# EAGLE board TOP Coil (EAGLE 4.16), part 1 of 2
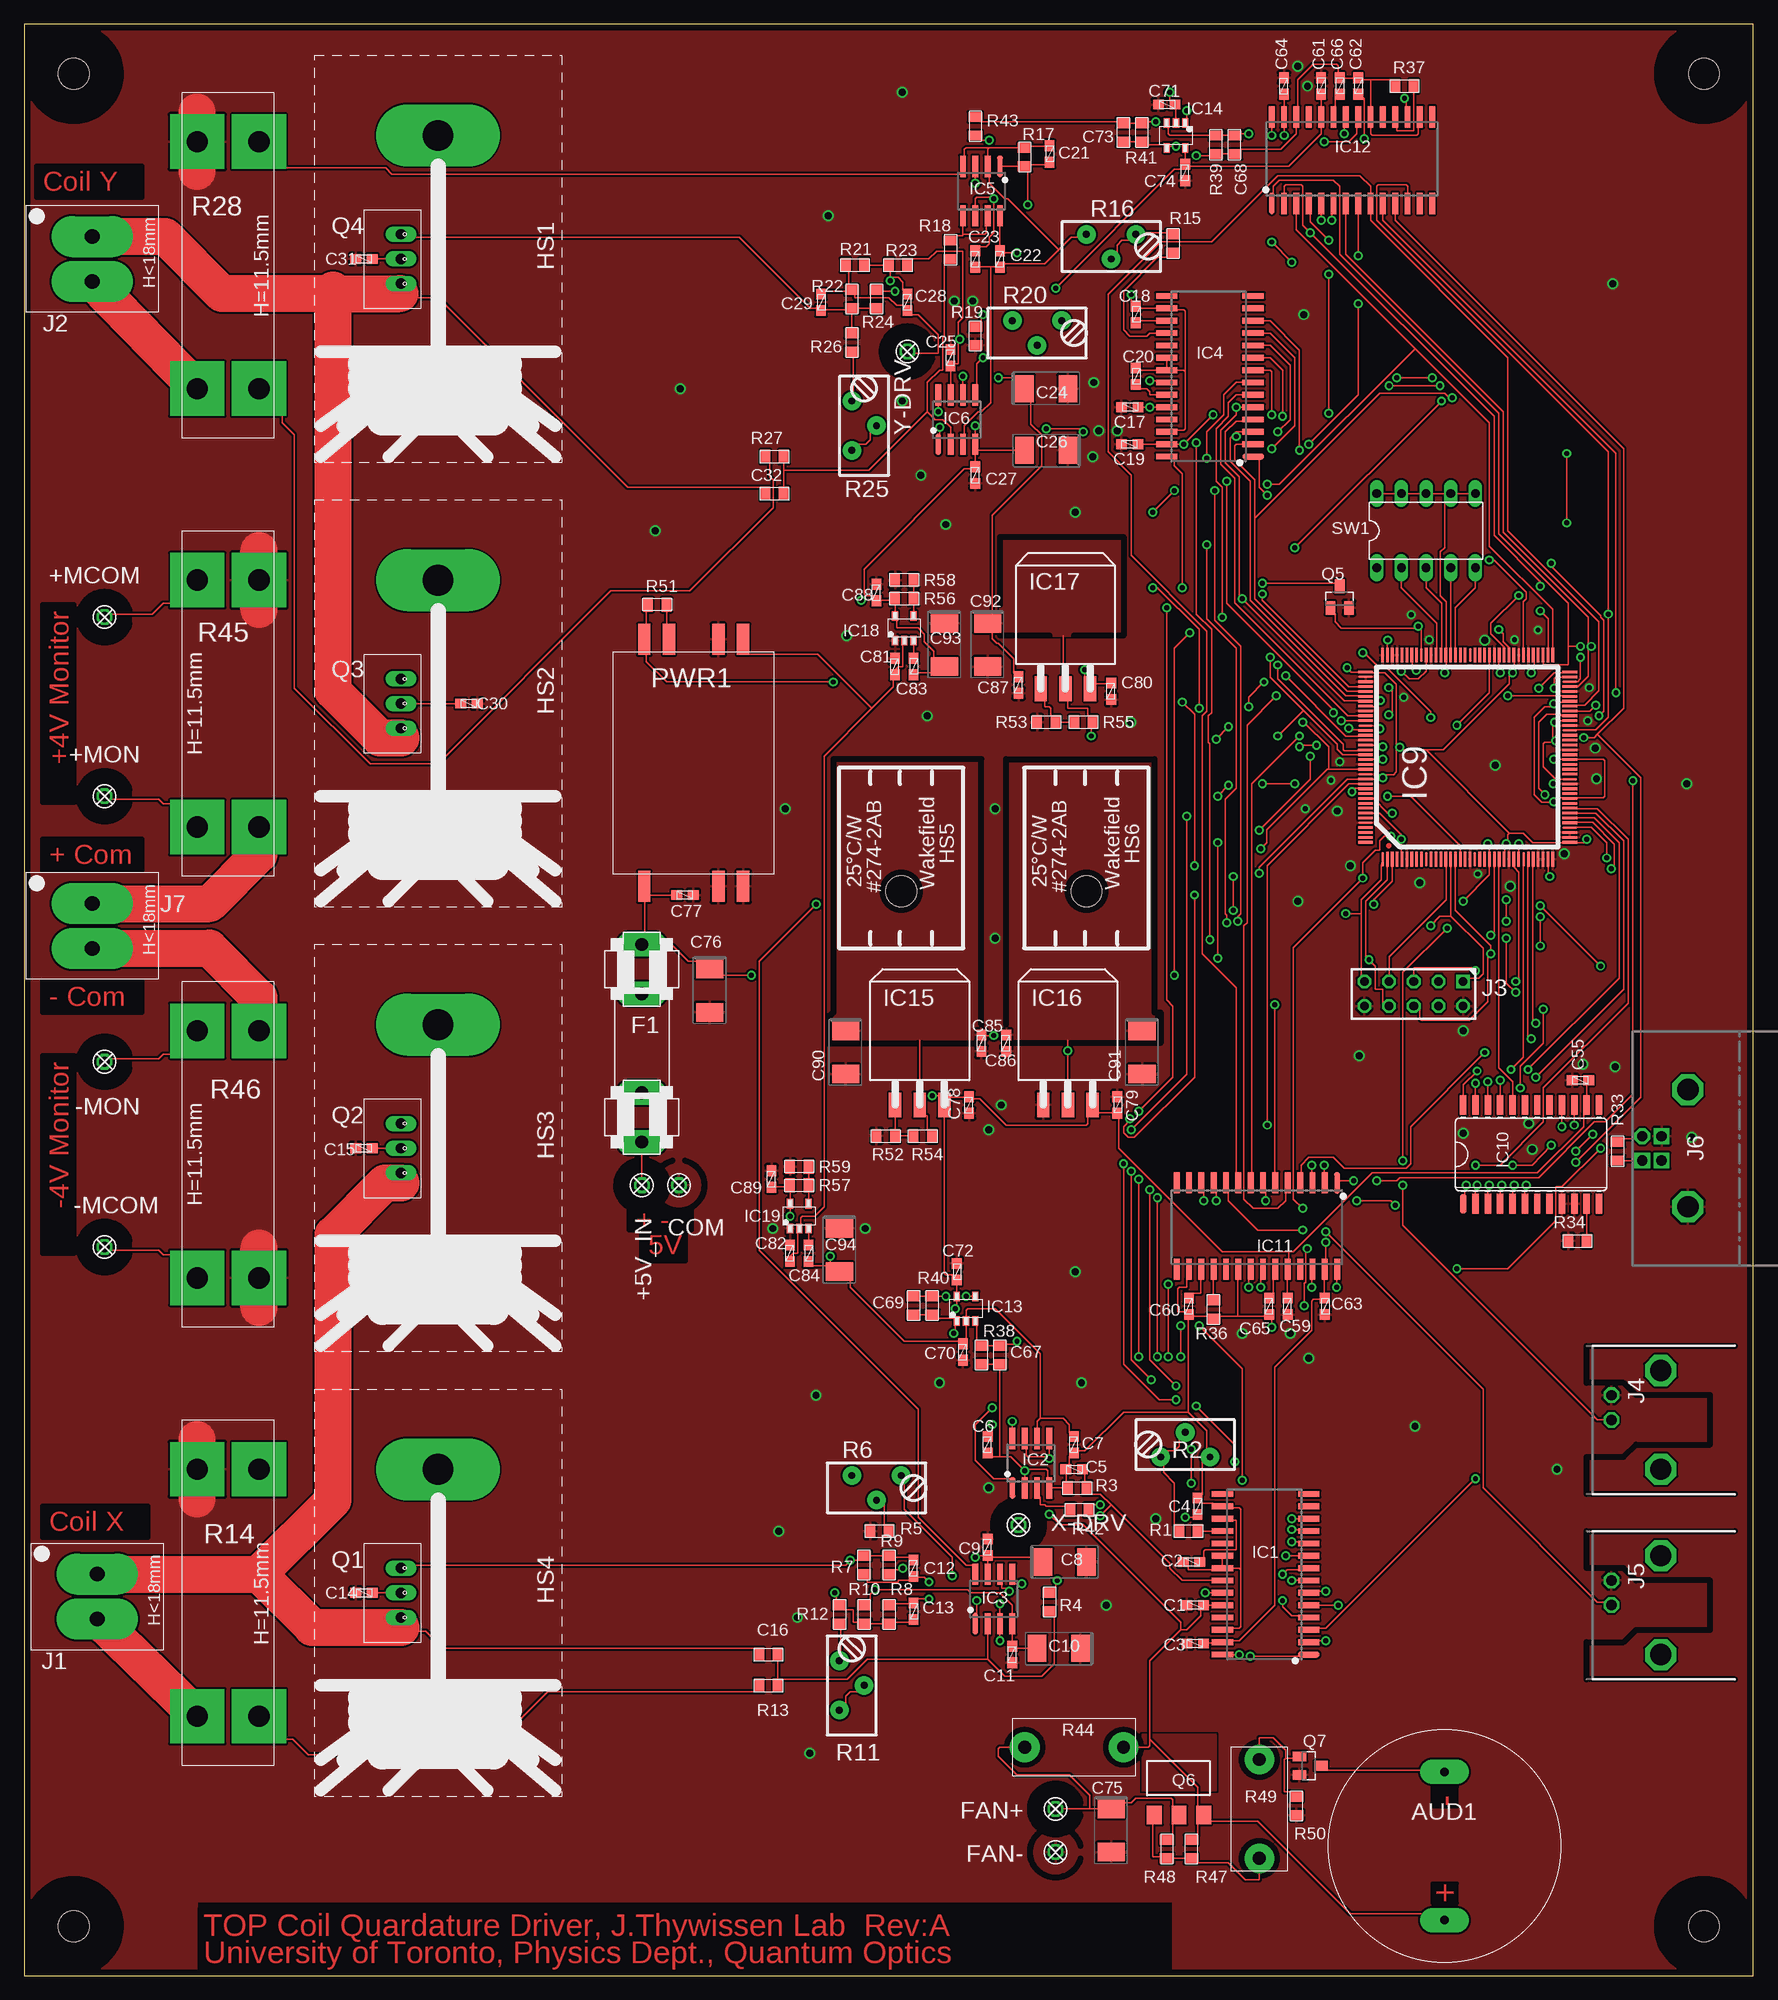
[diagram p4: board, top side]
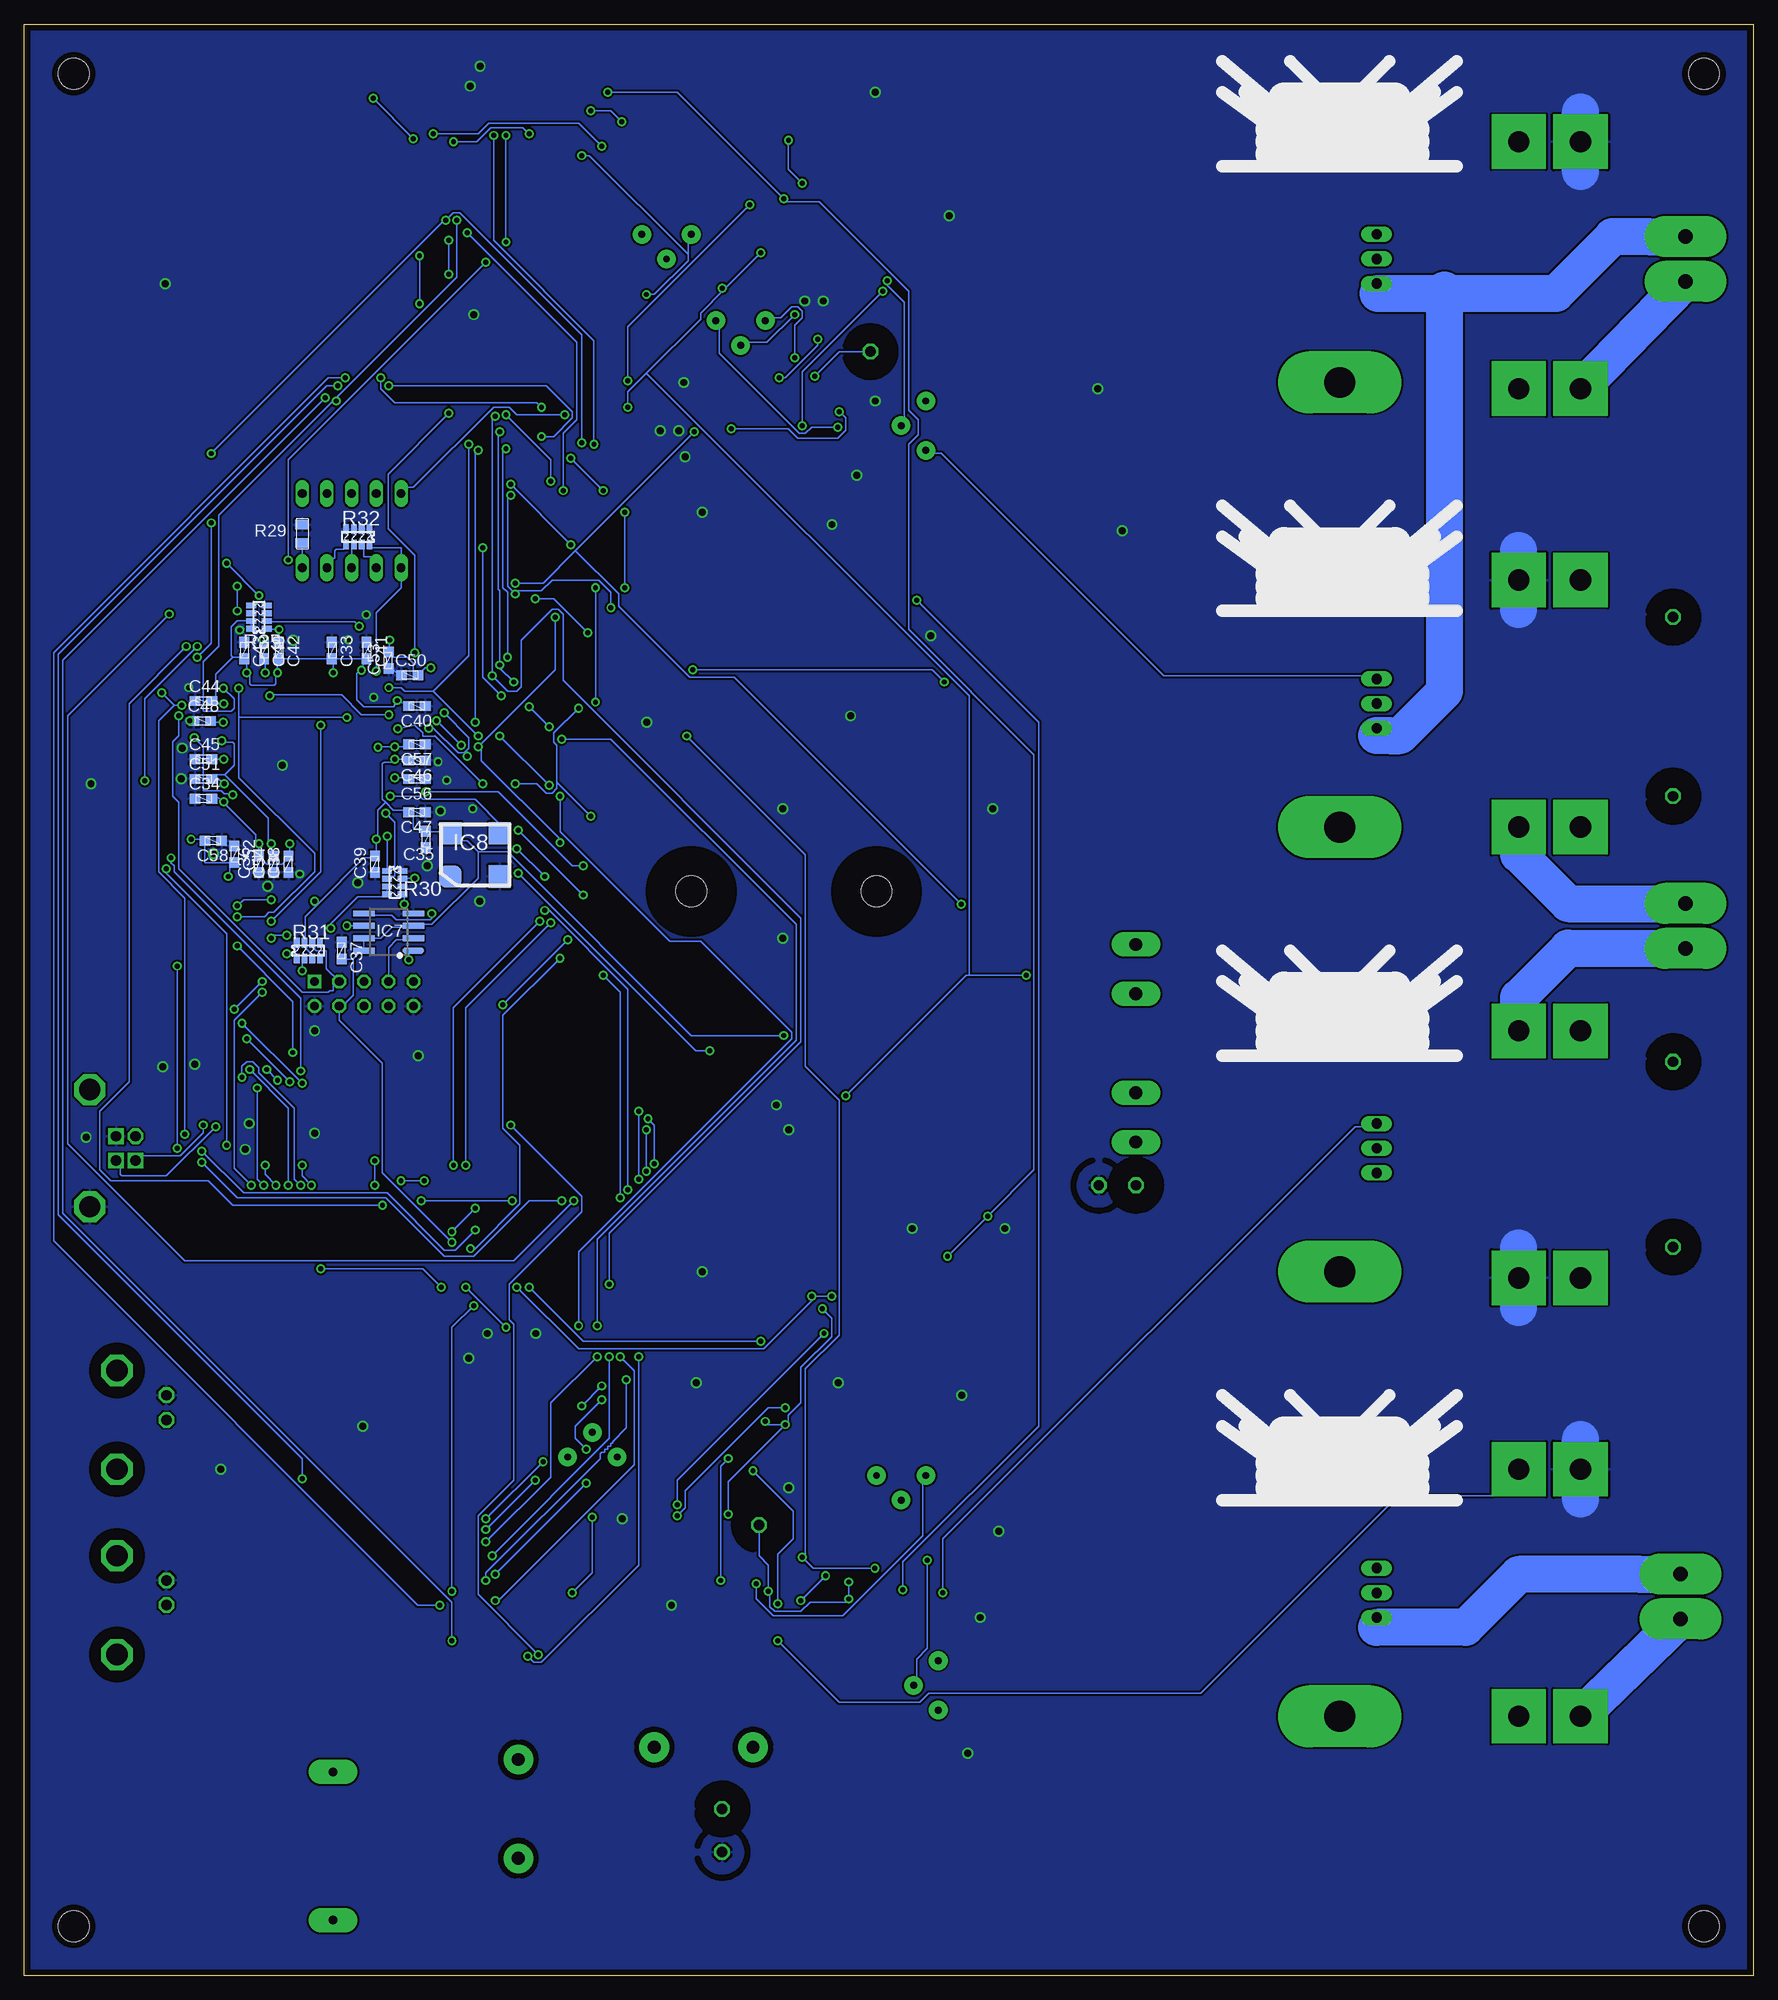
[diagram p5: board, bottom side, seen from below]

Size 177.8 x 200.66 mm. Coordinates in mm from the lower left corner, seen from the top.
Outline: 0,0 177.8,0 177.8,200.66 0,200.66 0,0
Copper layers (1*16): Top 0.035mm / dielectric 1.5mm / Bottom 0.035mm
Design rules "DRC standard check (7mil trace and gap, 20mil drill, etc)": minimum track width 7mil, minimum drill 20mil, track to track 7mil, track to pad 7mil, pad to pad 7mil, via to via 7mil, smd to smd 7mil, copper to edge 25mil, drill to drill 8mil, minimum pad ring 10mil, minimum via ring 8mil, stop-mask expansion 4mil, vias tented up to drill 0mil, thermal gap 10mil
Holes 3.17 mm at 5.08,5.08 172.72,5.08 5.08,195.58 172.72,195.58
tKeepout: area -0.2,-0.2 to 10.3,10.3; area 167.5,-0.2 to 178,10.3; area -0.2,190.3 to 10.3,200.8; area 167.5,190.3 to 178,200.8
bKeepout: area -0.2,-0.2 to 10.3,10.3; area 167.5,-0.2 to 178,10.3; area -0.2,190.3 to 10.3,200.8; area 167.5,190.3 to 178,200.8
tRestrict: 58 lines
bRestrict: 6 lines
vRestrict: area 83.2,95.9 to 98.4,125.1; area 101,95.9 to 116.2,125.1; area 100.3,137.8 to 113,148

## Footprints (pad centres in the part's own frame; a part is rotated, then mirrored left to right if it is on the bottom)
TP-0.042 = drill 1.067 octagon: TP 0,0
AUDIO_DEVICE1 = drill 0.889 pad 2.54 long: + -7.62,0; - 7.62,0
1608(0603) = smd 1.1 x 1: 1 -0.85,0; 2 0.85,0
EIA-6032 = smd 1.905 x 2.794: + 2.54,0; - -1.905,0
2012(0805) = smd 1.016 x 1.397: 1 -1.27,0; 2 0.635,0
FUSE = drill 1.321 pad 2.54 long: 1A -10.16,0; 1B -5.08,0; 2A 10.16,0; 2B 5.08,0
HEATSINK_529802B02(AAVID) = drill 3.175 pad 6.35 long: 1 -12.7,0; 2 12.7,0
HEATSINK-3 = hole 3.175: 3.429,0
SOIC28 = smd 0.6 x 2.2: 1 -7.62,-3.81; 2 -6.35,-3.81; 3 -5.08,-3.81; 4 -3.81,-3.81; 5 -2.54,-3.81; 6 -1.27,-3.81; 7 0,-3.81; 8 1.27,-3.81; 9 2.54,-3.81; 10 3.81,-3.81; 11 5.08,-3.81; 12 6.35,-3.81; 13 7.62,-3.81; 14 8.89,-3.81; 15 8.89,5.08; 16 7.62,5.08; 17 6.35,5.08; 18 5.08,5.08; 19 3.81,5.08; 20 2.54,5.08; 21 1.27,5.08; 22 0,5.08; 23 -1.27,5.08; 24 -2.54,5.08; 25 -3.81,5.08; 26 -5.08,5.08; 27 -6.35,5.08; 28 -7.62,5.08
SOIC-8 = smd 0.6 x 2.2: 1 -1.27,-2.54; 2 0,-2.54; 3 1.27,-2.54; 4 2.54,-2.54; 5 2.54,2.54; 6 1.27,2.54; 7 0,2.54; 8 -1.27,2.54
CSX750(CITIZEN_OSC) = smd 2.286 x 2.286: 1 -2.54,-1.27; 2 2.54,-1.27; 3 2.54,3.175; 4 -2.54,3.175
TQFP-144 = smd 1.5 x 0.27: 1 -10.29,8.29; 2 -10.29,7.79; 3 -10.29,7.29; 4 -10.29,6.79; 5 -10.29,6.29; 6 -10.29,5.79; 7 -10.29,5.29; 8 -10.29,4.79; 9 -10.29,4.29; 10 -10.29,3.79; 11 -10.29,3.29; 12 -10.29,2.79; 13 -10.29,2.29; 14 -10.29,1.79; 15 -10.29,1.29; 16 -10.29,0.79; 17 -10.29,0.29; 18 -10.29,-0.21; 19 -10.29,-0.71; 20 -10.29,-1.21; 21 -10.29,-1.71; 22 -10.29,-2.21; 23 -10.29,-2.71; 24 -10.29,-3.21; 25 -10.29,-3.71; 26 -10.29,-4.21; 27 -10.29,-4.71; 28 -10.29,-5.21; 29 -10.29,-5.71; 30 -10.29,-6.21; 31 -10.29,-6.71; 32 -10.29,-7.21; 33 -10.29,-7.71; 34 -10.29,-8.21; 35 -10.29,-8.71; 36 -10.29,-9.21; 73 10.71,-9.21; 74 10.71,-8.71; 75 10.71,-8.21; 76 10.71,-7.71; 77 10.71,-7.21; 78 10.71,-6.71; 79 10.71,-6.21; 80 10.71,-5.71; 81 10.71,-5.21; 82 10.71,-4.71; 83 10.71,-4.21; 84 10.71,-3.71; 85 10.71,-3.21; 86 10.71,-2.71; 87 10.71,-2.21; 88 10.71,-1.71; 89 10.71,-1.21; 90 10.71,-0.71; 91 10.71,-0.21; 92 10.71,0.29; 93 10.71,0.79; 94 10.71,1.29; 95 10.71,1.79; 96 10.71,2.29; 97 10.71,2.79; 98 10.71,3.29; 99 10.71,3.79; 100 10.71,4.29; 101 10.71,4.79; 102 10.71,5.29; 103 10.71,5.79; 104 10.71,6.29; 105 10.71,6.79; 106 10.71,7.29; 107 10.71,7.79; 108 10.71,8.29 | smd 0.27 x 1.5: 37 -8.54,-10.96; 38 -8.04,-10.96; 39 -7.54,-10.96; 40 -7.04,-10.96; 41 -6.54,-10.96; 42 -6.04,-10.96; 43 -5.54,-10.96; 44 -5.04,-10.96; 45 -4.54,-10.96; 46 -4.04,-10.96; 47 -3.54,-10.96; 48 -3.04,-10.96; 49 -2.54,-10.96; 50 -2.04,-10.96; 51 -1.54,-10.96; 52 -1.04,-10.96; 53 -0.54,-10.96; 54 -0.04,-10.96; 55 0.46,-10.96; 56 0.96,-10.96; 57 1.46,-10.96; 58 1.96,-10.96; 59 2.46,-10.96; 60 2.96,-10.96; 61 3.46,-10.96; 62 3.96,-10.96; 63 4.46,-10.96; 64 4.96,-10.96; 65 5.46,-10.96; 66 5.96,-10.96; 67 6.46,-10.96; 68 6.96,-10.96; 69 7.46,-10.96; 70 7.96,-10.96; 71 8.46,-10.96; 72 8.96,-10.96; 109 8.96,10.04; 110 8.46,10.04; 111 7.96,10.04; 112 7.46,10.04; 113 6.96,10.04; 114 6.46,10.04; 115 5.96,10.04; 116 5.46,10.04; 117 4.96,10.04; 118 4.46,10.04; 119 3.96,10.04; 120 3.46,10.04; 121 2.96,10.04; 122 2.46,10.04; 123 1.96,10.04; 124 1.46,10.04; 125 0.96,10.04; 126 0.46,10.04; 127 -0.04,10.04; 128 -0.54,10.04; 129 -1.04,10.04; 130 -1.54,10.04; 131 -2.04,10.04; 132 -2.54,10.04; 133 -3.04,10.04; 134 -3.54,10.04; 135 -4.04,10.04; 136 -4.54,10.04; 137 -5.04,10.04; 138 -5.54,10.04; 139 -6.04,10.04; 140 -6.54,10.04; 141 -7.04,10.04; 142 -7.54,10.04; 143 -8.04,10.04; 144 -8.54,10.04
SOIC-24-0.3 = smd 0.66 x 2.032: 1 -6.35,-5.08; 2 -5.08,-5.08; 3 -3.81,-5.08; 4 -2.54,-5.08; 5 -1.27,-5.08; 6 0,-5.08; 7 1.27,-5.08; 8 2.54,-5.08; 9 3.81,-5.08; 10 5.08,-5.08; 11 6.35,-5.08; 12 7.62,-5.08; 13 7.62,5.08; 14 6.35,5.08; 15 5.08,5.08; 16 3.81,5.08; 17 2.54,5.08; 18 1.27,5.08; 19 0,5.08; 20 -1.27,5.08; 21 -2.54,5.08; 22 -3.81,5.08; 23 -5.08,5.08; 24 -6.35,5.08
SOT23-5 = smd 0.635 x 0.991: 1 -0.635,-1.27; 2 0.318,-1.27; 3 1.27,-1.27; 4 1.27,1.27; 5 -0.635,1.27
TO263 = smd 1.27 x 2.54: 1 -2.54,0; 2 0,0; 3 2.54,0
CONN-2TERM = drill 1.511 pad 4.2 long: 1 0,2.31; 2 0,-2.31
CONN-2X5-BLASTER = drill 0.889 square: 1 0,5.08 | drill 0.889 octagon: 2 2.54,5.08; 3 0,2.54; 4 2.54,2.54; 5 0,0; 6 2.54,0; 7 0,-2.54; 8 2.54,-2.54; 9 0,-5.08; 10 2.54,-5.08
CONN-BNC-AMP-TYPE3HORIZ = drill 1.067 octagon: CONDUCTOR 0,-12.7; SHIELD -2.54,-12.7 | drill 2.184 octagon: P$1 -5.08,-7.62; P$2 5.08,-7.62
CONN-USB_AU-Y1007 = drill 1.067 octagon: 1 2.5,0 | drill 1.067 square: 2 0,0; 3 0,-2; 4 2.5,-2 | drill 2.184 octagon: S1 -4.75,-4.7; S2 7.3,-4.7
CC3-XXXXX-E(TDK_DC-DC) = smd 3.175 x 1.27: +VIN -12.7,5.08; +VOUT 12.7,5.08; -VIN -12.7,-5.08; -VOUT 12.7,-5.08; COM 12.7,-2.54; RC -12.7,-2.54; TRM 12.7,2.54
TO220-VERTICAL = drill 1.067 long: 1 -2.54,0; 2 0,0; 3 2.54,0
SOT23 = smd 1 x 1.4: 1 -0.953,-0.953; 2 0.953,-0.953; 3 0,1.27
SOT223 = smd 1.524 x 1.905: 1 -2.54,-2.54; 2 0,-2.54; 3 2.54,-2.54
BOURNS-3296Y = drill 0.711 pad 1.905 round: CCW 2.54,1.27; CW -2.54,1.27; W 0,-1.27
OHMITE_650 = drill 2.184 pad 5.588 square: 1A -12.7,2.54; 1B -12.7,-3.81; 2A 12.7,2.54; 2B 12.7,-3.81
PANASONIC_EXB-V8V(QUAD-R-PACK) = smd 1 x 0.59: 1A -0.8,1.2; 1B 0.8,1.2; 2A -0.8,0.4; 2B 0.8,0.4; 3A -0.8,-0.4; 3B 0.8,-0.4; 4A -0.8,-1.2; 4B 0.8,-1.2
PASSIVE_0.4" = drill 1.321 pad 3.048 round: 1 -5.08,0; 2 5.08,0
DIL10 = drill 0.889 long: 1 -6.35,-3.81; 2 -3.81,-3.81; 3 -1.27,-3.81; 4 1.27,-3.81; 5 3.81,-3.81; 6 3.81,3.81; 7 1.27,3.81; 8 -1.27,3.81; 9 -3.81,3.81; 10 -6.35,3.81

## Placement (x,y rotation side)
+5V_IN  [TP-0.042]  63.5,81.28 270 top
+MCOM  [TP-0.042]  8.26,139.7 180 top
+MON  [TP-0.042]  8.26,121.28 180 top
-MCOM  [TP-0.042]  8.26,74.93 180 top
-MON  [TP-0.042]  8.26,93.98 180 top
AUD1  MSR516W*  [AUDIO_DEVICE1]  146.05,13.34 90 top
C1  0.1uF  [1608(0603)]  120.4,38.1 0 top
C2  0.1uF  [1608(0603)]  120.02,42.55 0 top
C3  0.1uF  [1608(0603)]  120.4,34.16 180 top
C4  0.1uF  [1608(0603)]  120.65,48.26 270 top
C5  0.1uF  [1608(0603)]  107.95,52.07 0 top
C6  0.1uF  [1608(0603)]  99.06,54.61 90 top
C7  0.1uF  [1608(0603)]  107.95,54.61 90 top
C8  33uF*  [EIA-6032]  107.31,42.55 180 top
C9  0.1uF  [1608(0603)]  99.06,44.07 90 top
C10  33uF*  [EIA-6032]  106.05,33.66 0 top
C11  0.1uF  [1608(0603)]  101.6,33.02 90 top
C12  1uF  [1608(0603)]  91.44,41.91 90 top
C13  1uF  [1608(0603)]  91.44,37.47 270 top
C14  0.1uF  [1608(0603)]  34.92,39.37 0 top
C15  0.1uF  [1608(0603)]  34.92,85.09 180 top
C16  22pF  [2012(0805)]  76.83,33.02 0 top
C17  0.1uF  [1608(0603)]  113.67,161.29 0 top
C18  0.1uF  [1608(0603)]  114.3,170.81 270 top
C19  0.1uF  [1608(0603)]  113.67,157.48 180 top
C20  0.1uF  [1608(0603)]  114.3,164.47 270 top
C21  0.1uF  [1608(0603)]  105.41,187.32 270 top
C22  0.1uF  [1608(0603)]  100.33,176.53 90 top
C23  0.1uF  [1608(0603)]  97.79,176.53 90 top
C24  33uF*  [EIA-6032]  105.41,163.19 180 top
C25  0.1uF  [1608(0603)]  95.25,166.37 90 top
C26  33uF*  [EIA-6032]  104.78,156.84 0 top
C27  0.1uF  [1608(0603)]  97.79,154.31 90 top
C28  1uF  [1608(0603)]  90.81,172.09 90 top
C29  1uF  [1608(0603)]  81.92,172.09 270 top
C30  0.1uF  [1608(0603)]  45.72,130.81 180 top
C31  0.1uF  [1608(0603)]  34.92,176.53 180 top
C32  22pF  [2012(0805)]  77.47,152.4 0 top
C33  0.1uF  [1608(0603)]  146.18,136.27 270 bottom
C34  0.1uF  [1608(0603)]  159.38,121.03 0 bottom
C35  0.1uF  [1608(0603)]  136.53,116.84 270 bottom
C36  0.1uF  [1608(0603)]  153.67,114.3 90 bottom
C37  0.1uF  [1608(0603)]  145.16,105.41 90 bottom
C38  0.1uF  [1608(0603)]  150.62,114.3 90 bottom
C39  0.1uF  [1608(0603)]  141.73,114.3 90 bottom
C40  0.1uF  [1608(0603)]  137.41,130.56 180 bottom
C41  0.1uF  [1608(0603)]  142.62,136.27 270 bottom
C42  0.1uF  [1608(0603)]  151.64,136.27 270 bottom
C43  0.1uF  [1608(0603)]  155.19,136.27 270 bottom
C44  0.1uF  [1608(0603)]  159.38,131.06 0 bottom
C45  0.1uF  [1608(0603)]  159.38,125.09 0 bottom
C46  0.1uF  [1608(0603)]  137.41,124.97 180 bottom
C47  0.1uF  [1608(0603)]  137.41,119.63 180 bottom
C48  0.1uF  [1608(0603)]  159.51,129.03 0 bottom
C49  0.1uF  [1608(0603)]  153.16,136.27 270 bottom
C50  0.1uF  [1608(0603)]  138.18,133.73 0 bottom
C51  0.1uF  [1608(0603)]  159.38,123.06 0 bottom
C52  0.1uF  [1608(0603)]  156.21,115.32 270 bottom
C53  0.1uF  [1608(0603)]  140.34,135.25 90 bottom
C54  0.1uF  [1608(0603)]  152.15,114.3 90 bottom
C55  0.1uF  [1608(0603)]  160.02,92.08 180 top
C56  0.1uF  [1608(0603)]  137.41,123.06 180 bottom
C57  0.1uF  [1608(0603)]  137.41,126.62 180 bottom
C58  0.1uF  [1608(0603)]  158.37,116.71 180 bottom
C59  0.1uF  [1608(0603)]  129.92,68.83 90 top
C60  0.1uF  [1608(0603)]  119.76,68.83 90 top
C61  0.1uF  [1608(0603)]  133.35,194.31 270 top
C62  0.1uF  [1608(0603)]  137.16,194.31 270 top
C63  0.1uF  [1608(0603)]  133.73,68.83 270 top
C64  0.1uF  [1608(0603)]  129.54,194.31 90 top
C65  0.1uF  [1608(0603)]  128.02,68.83 90 top
C66  0.1uF  [1608(0603)]  135.25,194.31 270 top
C67  27nF  [2012(0805)]  100.33,64.14 90 top
C68  27nF  [2012(0805)]  124.46,188.59 90 top
C69  27nF  [2012(0805)]  91.44,68.58 270 top
C70  0.1uF  [1608(0603)]  96.52,64.14 90 top
C71  0.1uF  [1608(0603)]  117.47,192.41 0 top
C72  0.1uF  [1608(0603)]  95.89,72.39 270 top
C73  27nF  [2012(0805)]  113.03,189.87 90 top
C74  0.1uF  [1608(0603)]  119.38,185.42 90 top
C75  33uF*  [EIA-6032]  111.76,14.61 90 top
C76  33uF*  [EIA-6032]  70.48,100.97 90 top
C77  0.1uF  [1608(0603)]  67.94,111.12 180 top
C78  0.1uF  [1608(0603)]  97.16,89.53 90 top
C79  0.1uF  [1608(0603)]  112.39,89.53 270 top
C80  0.1uF  [1608(0603)]  111.76,132.08 90 top
C81  0.1uF  [1608(0603)]  89.53,134.62 90 top
C82  0.1uF  [1608(0603)]  78.74,74.3 90 top
C83  0.1uF  [1608(0603)]  91.44,134.62 270 top
C84  0.1uF  [1608(0603)]  80.64,74.3 270 top
C85  0.1uF  [1608(0603)]  98.42,95.89 90 top
C86  0.1uF  [1608(0603)]  100.97,95.89 90 top
C87  0.1uF  [1608(0603)]  102.23,132.72 90 top
C88  0.1uF  [1608(0603)]  87.63,142.24 90 top
C89  0.1uF  [1608(0603)]  76.83,81.92 90 top
C90  33uF*  [EIA-6032]  84.45,94.61 90 top
C91  33uF*  [EIA-6032]  114.94,94.61 90 top
C92  33uF*  [EIA-6032]  99.06,136.53 90 top
C93  33uF*  [EIA-6032]  94.61,136.53 90 top
C94  33uF*  [EIA-6032]  83.82,74.3 90 top
COM  [TP-0.042]  67.31,81.28 270 top
F1  1A  [FUSE]  63.5,95.89 90 top
FAN+  [TP-0.042]  106.05,17.14 180 top
FAN-  [TP-0.042]  106.05,12.7 180 top
HS1  529802B02500G  [HEATSINK_529802B02(AAVID)]  42.55,176.53 270 top
HS2  529802B02500G  [HEATSINK_529802B02(AAVID)]  42.55,130.81 270 top
HS3  529802B02500G  [HEATSINK_529802B02(AAVID)]  42.55,85.09 270 top
HS4  529802B02500G  [HEATSINK_529802B02(AAVID)]  42.55,39.37 270 top
HS5  274-2AB  [HEATSINK-3]  90.17,114.94 270 top
HS6  274-2AB  [HEATSINK-3]  109.22,114.94 270 top
IC1  AD9752ARZ  [SOIC28]  128.27,40.64 90 top
IC2  AD603AR  [SOIC-8]  102.87,52.7 0 top
IC3  AD810AR  [SOIC-8]  99.06,38.73 0 top
IC4  AD9752ARZ  [SOIC28]  122.56,163.83 90 top
IC5  AD603AR  [SOIC-8]  99.06,183.51 180 top
IC6  AD810AR  [SOIC-8]  95.25,160.02 0 top
IC7  EPCS4  [SOIC-8]  140.34,106.68 90 bottom
IC8  80MHz*  [CSX750(CITIZEN_OSC)]  131.44,114.3 0 bottom
IC9  EP2C8T144C6  [TQFP-144]  147.96,125.09 90 top
IC10  802600*  [SOIC-24-0.3]  154.31,84.45 0 top
IC11  AD9752ARZ  [SOIC28]  127.38,77.72 180 top
IC12  AD9752ARZ  [SOIC28]  135.89,186.06 0 top
IC13  AD8614ART  [SOT23-5]  96.52,68.58 0 top
IC14  AD8614ART  [SOT23-5]  118.75,189.23 180 top
IC15  LM1086-ADJ  [TO263]  92.08,89.53 0 top
IC16  LM1086-ADJ  [TO263]  107.31,89.53 0 top
IC17  LM1086-ADJ  [TO263]  107.06,132.33 0 top
IC18  LT1964ES5-BYP  [SOT23-5]  90.17,138.56 0 top
IC19  LT1964ES5-BYP  [SOT23-5]  79.38,78.11 0 top
J1  LPP-5.00/90*  [CONN-2TERM]  7.49,38.99 0 top
J2  LPP-5.00/90*  [CONN-2TERM]  6.99,176.53 0 top
J3  2x5*  [CONN-2X5-BLASTER]  142.88,102.23 270 top
J4  227677-1*  [CONN-BNC-AMP-TYPE3HORIZ]  175.9,57.15 270 top
J5  227677-1*  [CONN-BNC-AMP-TYPE3HORIZ]  175.9,38.1 270 top
J6  (see BOM*)  [CONN-USB_AU-Y1007]  166.37,83.82 90 top
J7  LPP-5.00/90  [CONN-2TERM]  6.99,107.95 0 top
PWR1  CC3-0512DR-E  [CC3-XXXXX-E(TDK_DC-DC)]  68.83,124.71 90 top
Q1  NTP90N02  [TO220-VERTICAL]  38.73,39.37 270 top
Q2  MTP50P03HDL  [TO220-VERTICAL]  38.73,85.09 270 top
Q3  NTP90N02  [TO220-VERTICAL]  38.73,130.81 270 top
Q4  MTB50P03HDL  [TO220-VERTICAL]  38.73,176.53 270 top
Q5  2N7002  [SOT23]  135.25,141.6 0 top
Q6  FZT948  [SOT223]  118.75,19.05 0 top
Q7  MMBT5551-TP  [SOT23]  132.08,21.59 270 top
R1  1.50K  [2012(0805)]  120.02,45.72 0 top
R2  3296Y-1K*  [BOURNS-3296Y]  119.38,54.61 180 top
R3  64.9  [2012(0805)]  108.58,50.16 0 top
R4  2K  [2012(0805)]  105.41,38.1 270 top
R5  75K  [2012(0805)]  88.27,45.72 0 top
R6  3296Y-10K*  [BOURNS-3296Y]  87.63,50.16 0 top
R7  1K  [2012(0805)]  86.36,42.55 90 top
R8  1K  [2012(0805)]  88.9,36.83 270 top
R9  1K  [2012(0805)]  88.9,41.91 270 top
R10  1K  [2012(0805)]  86.36,36.83 270 top
R11  3296Y-1K*  [BOURNS-3296Y]  85.09,29.84 90 top
R12  1K  [2012(0805)]  83.82,36.83 270 top
R13  100  [2012(0805)]  76.83,29.84 0 top
R14  5mOhm*  [OHMITE_650]  20.32,39.37 90 top
R15  1.50K  [2012(0805)]  118.11,177.8 270 top
R16  3296Y-1K*  [BOURNS-3296Y]  111.76,177.8 0 top
R17  64.9  [2012(0805)]  102.87,186.69 270 top
R18  2K  [2012(0805)]  95.25,177.16 270 top
R19  75K  [2012(0805)]  97.79,168.91 90 top
R20  3296Y-10K*  [BOURNS-3296Y]  104.14,168.91 0 top
R21  1K  [2012(0805)]  85.72,175.9 0 top
R22  1K  [2012(0805)]  85.09,172.09 270 top
R23  1K  [2012(0805)]  90.17,175.9 0 top
R24  1K  [2012(0805)]  87.63,172.09 270 top
R25  3296Y-1K*  [BOURNS-3296Y]  86.36,159.38 90 top
R26  1K  [2012(0805)]  85.09,167.64 270 top
R27  100  [2012(0805)]  77.47,156.21 0 top
R28  5mOhm*  [OHMITE_650]  20.32,175.9 90 top
R29  10K  [2012(0805)]  149.22,147.96 270 bottom
R30  10K  [PANASONIC_EXB-V8V(QUAD-R-PACK)]  139.7,112.39 0 bottom
R31  10K  [PANASONIC_EXB-V8V(QUAD-R-PACK)]  148.59,105.41 90 bottom
R32  10K  [PANASONIC_EXB-V8V(QUAD-R-PACK)]  143.51,147.96 270 bottom
R33  7.50K  [2012(0805)]  163.83,84.45 270 top
R34  7.50K  [2012(0805)]  160.02,75.56 0 top
R35  10K  [PANASONIC_EXB-V8V(QUAD-R-PACK)]  153.67,139.7 180 bottom
R36  2K  [2012(0805)]  122.3,68.83 90 top
R37  2K  [2012(0805)]  142.24,194.31 0 top
R38  100  [2012(0805)]  98.42,64.14 90 top
R39  100  [2012(0805)]  122.56,188.59 90 top
R40  100  [2012(0805)]  93.34,68.58 270 top
R41  100  [2012(0805)]  114.94,189.87 90 top
R42  49.9K  [2012(0805)]  108.2,47.88 180 top
R43  49.9K  [2012(0805)]  97.79,189.87 270 top
R44  ???  [PASSIVE_0.4"]  107.95,23.5 0 top
R45  5mOhm  [OHMITE_650]  21.59,130.81 270 top
R46  5mOhm  [OHMITE_650]  21.59,84.45 270 top
R47  100K  [2012(0805)]  117.47,12.7 270 top
R48  100  [2012(0805)]  120.02,13.34 90 top
R49  ERT-D2FGL102S*  [PASSIVE_0.4"]  127,17.14 270 top
R50  ???  [2012(0805)]  130.81,17.78 90 top
R51  750  [2012(0805)]  64.77,140.97 180 top
R52  200  [2012(0805)]  88.9,86.36 0 top
R53  549  [2012(0805)]  105.41,128.91 0 top
R54  121  [2012(0805)]  92.71,86.36 0 top
R55  121  [2012(0805)]  109.22,128.91 0 top
R56  1K  [2012(0805)]  90.81,141.6 0 top
R57  1K  [2012(0805)]  80.01,81.28 0 top
R58  4.75K  [2012(0805)]  90.17,143.51 180 top
R59  4.75K  [2012(0805)]  79.38,83.19 180 top
SW1  (see BOM*)  [DIL10]  145.41,148.59 0 top
U$20  [TITLEBLOCK_PCB]  not placed on the board
X-DRV  [TP-0.042]  102.23,46.35 90 top
Y-DRV  [TP-0.042]  90.81,167 180 top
